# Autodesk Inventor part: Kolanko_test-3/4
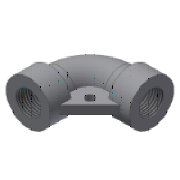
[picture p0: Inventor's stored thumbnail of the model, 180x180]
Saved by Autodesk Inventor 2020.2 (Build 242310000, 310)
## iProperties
Manager: www.cadconsulting.pl
Company: Fabian Stasiak CAD Consulting
Created: 2014-08
Part Number: Kolanko_test-3/4
Material: Ogólny
Document SubType Name: Modeling
Designer: F.Stasiak
Language: pl-PL
Size Designation: 3/4
Categories: <MemberInstance><Categories><Category DisplayName="Rury cienko- i grubościenne" InternalName="4347fa0f-2144-441d-94cd-e3e15c92b736" Mnemonic="TUBEANDPIPE"><Cate
Density: 1 g/cm^3
Appearance: Domyślna
Catalog Web Link: www.expertbooks.pl
IsCustomPart: 0
Author: F.Stasiak
Subject: Zbiór ćwiczeń. Autodesk Inventor 2020. Kurs Professional
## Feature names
1. Przeciągnięcie1
2. Wyciągnięcie proste1 [Extrusion]
3. Wyciągnięcie proste2 [Extrusion]
4. Wyciągnięcie proste5 [Extrusion]
## Parameters: d0 = 59.182 mm, d1 = 59.182 mm, d2 = 29.591 mm, d4 = 0, d5 = 0, d6 = 38.1 mm, d7 = 23.6728 mm, d9 = 18.3134 mm, d10 = 0, d11 = 38.1 mm, d12 = 18.3134 mm, d13 = 0, d19 = 19.8628 mm, d20 = 0, d21 = 19.8628 mm, d22 = 0, ID = 23.6728 mm, OD = 38.1 mm, GL = 18.3134 mm, G = 3.429 mm, d23 = 3.429 mm, d24 = 6.35 mm, d26 = 6.858 mm, d27 = 0
